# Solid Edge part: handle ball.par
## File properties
Title: Handle Ball
Author: Abhinva Rai
Template: Normal.par
Last saved by: Cadcim
Revision: 10
Application: Solid Edge
Density: 0.0000078 kg/mm^3
Accuracy: 0.01
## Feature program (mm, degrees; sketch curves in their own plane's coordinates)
sketch for "unnamed RevolvedProtrusion 1" plane through (0, 0, 0) normal (0, -1, 0) x-axis (1, 0, 0)
  arc centre (0, 0) radius 9.525 from (0, 9.525) to (0, -9.525) cw
  line (0, 9.525) -> (0, -9.525)
revolve "unnamed RevolvedProtrusion 1" add finite 360 deg
sketch for "unnamed Cutout 1" plane through (0, 0, 0) normal (0, -1, 0) x-axis (1, 0, 0)
  circle centre (0, 0) radius 3.9751
extrude "unnamed Cutout 1" cut finite 50.8 symmetric
sketch for "ExtrudedCutout_2" plane through (0, 0, 0) normal (0, 0, 1) x-axis (1, 0, 0)
  circle centre (0, 0) radius 1.905
extrude "ExtrudedCutout_2" cut finite 50.8 symmetric
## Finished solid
Body 1: solid body, 4 faces, 6 edges, 0 vertices.
  Faces by surface: cylinder 3, sphere 1
  Edges by curve: circle 4, intersection 2
Bounding box of the edges (mm; curved faces can reach further): 7.950 x 17.312 x 18.665, from (-3.9751, -8.6559, -9.3326) to (3.9751, 8.6559, 9.3326).
Cylindrical faces by radius (mm): R1.905 x2, R3.9751 x1
Spherical faces by radius (mm): R9.525 x1
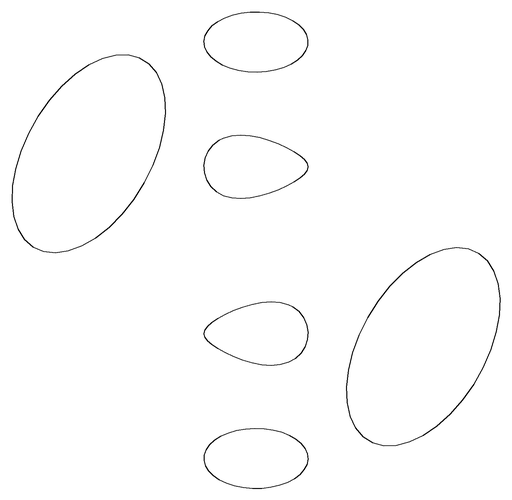
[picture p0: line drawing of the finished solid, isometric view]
